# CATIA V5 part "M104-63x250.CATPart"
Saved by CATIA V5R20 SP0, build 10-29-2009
Part number: M104-63x250
Source: Unknown
Bounding box of the stored display mesh (mm): x -31.459 to 31.459, y -31.459 to 31.459, z 0 to 250
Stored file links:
  C:\Users\Utente\Desktop\IO LAVORO\3D X SITO CF\X SITO\M104\M104-63x250.CATPart
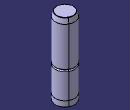
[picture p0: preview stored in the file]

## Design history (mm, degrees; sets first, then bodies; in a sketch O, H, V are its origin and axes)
Body1 (main body)
  Solid1 "PartBody": solid without history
